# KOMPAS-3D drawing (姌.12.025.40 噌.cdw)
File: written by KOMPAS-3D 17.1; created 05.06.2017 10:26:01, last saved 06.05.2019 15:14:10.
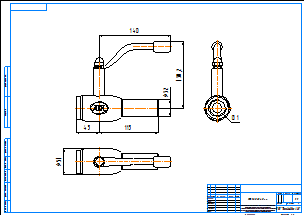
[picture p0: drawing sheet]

Sheet 1: A2, landscape

Title block, sheet 1: name: КШ.12.025.40 рс; material: Внимание! Данный продукт является объектом авторского права ООО «Торговый Дом АДЛ». / Запрещается изменение, копирование, распространение / (в том числе путем копирования на другие сайты и ресурсы в Интернете) / или любое иное использование информации и объектов без предварительного / согласия правообладателя (ООО «Торговый Дом АДЛ»).; sheets: 1; organisation: ООО "Торговый дом АДЛ"; sheet format: A2; stored path: C:\Users\kka\KOMPAS_Work\Модели кранов для исследований\Все краники\Редуцированный резьба-сварка ШК БИВАЛ\КШ.02.015.40 рс.cdw

Views: Вид 1, Проекционный вид 2, Проекционный вид 3
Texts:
  Klimkovich
  ADL
Dimensions and other numbers on the sheet: 140; 32; 45; 115; 130,2; 51; 1:1; 1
